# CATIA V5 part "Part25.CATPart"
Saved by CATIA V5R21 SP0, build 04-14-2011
Part number: Part25
Bounding box of the stored display mesh (mm): x 142.392 to 457.392, y 96.884 to 436.884, z 0 to 4
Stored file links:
  C:\Users\Administrator\Desktop\arm\Arm_Detailed_Design_Assembly_Manu\CAD\Part25.CATPart
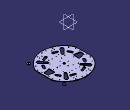
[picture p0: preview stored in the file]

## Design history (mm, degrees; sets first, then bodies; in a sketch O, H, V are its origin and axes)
Body1 (main body)
  Sketch1 on xy-plane, origin (0, 0, 0), H (1, 0, 0), V (0, 1, 0)
    circle A1 centre (152.3916, 324.3842) radius 2.5
    circle A2 centre (152.3916, 209.3842) radius 2.5
    circle A3 centre (242.3916, 414.3842) radius 2.5
    circle A4 centre (357.3916, 414.3842) radius 2.5
    circle A5 centre (447.3916, 324.3842) radius 2.5
    circle A6 centre (447.3916, 209.3842) radius 2.5
    circle A7 centre (242.3916, 119.3842) radius 2.5
    circle A8 centre (357.3916, 119.3842) radius 2.5
    arc A9 centre (299.8916, 266.8842) radius 170 from (144.0583, 198.9432) to (455.7249, 198.9432) ccw
    arc A10 centre (299.8916, 266.8842) radius 170 from (455.7249, 334.8251) to (144.0583, 334.8251) ccw
    arc A11 centre (162.3916, 206.9363) radius 20 from (142.3916, 206.9363) to (144.0583, 198.9432) ccw
    circle A12 centre (241.3916, 319.7117) radius 2
    circle A13 centre (241.3916, 399.7117) radius 2
    circle A14 centre (172.1096, 359.7117) radius 2
    circle A15 centre (358.3916, 319.7117) radius 2
    circle A16 centre (358.3916, 399.7117) radius 2
    circle A17 centre (427.6736, 359.7117) radius 2
    circle A18 centre (241.3916, 214.0566) radius 2
    circle A19 centre (241.3916, 134.0566) radius 2
    circle A20 centre (172.1096, 174.0566) radius 2
    circle A21 centre (358.3916, 214.0566) radius 2
    circle A22 centre (358.3916, 134.0566) radius 2
    circle A23 centre (427.6736, 174.0566) radius 2
    circle A24 centre (284.3916, 344.1678) radius 1.5
    circle A25 centre (315.3916, 344.1678) radius 1.5
    circle A26 centre (284.3916, 189.6006) radius 1.5
    circle A27 centre (315.3916, 189.6006) radius 1.5
    circle A28 centre (284.3916, 424.1678) radius 1.5
    circle A29 centre (315.3916, 424.1678) radius 1.5
    circle A30 centre (284.3916, 109.6006) radius 1.5
    circle A31 centre (315.3916, 109.6006) radius 1.5
    circle A32 centre (261.856, 348.4519) radius 1.5
    circle A33 centre (216.8916, 258.9342) radius 1.5
    circle A34 centre (337.9273, 348.4519) radius 1.5
    circle A35 centre (381.8916, 266.8842) radius 1.5
    circle A36 centre (261.856, 185.3165) radius 1.5
    circle A37 centre (337.9273, 185.3165) radius 1.5
    circle A38 centre (154.8916, 294.1984) radius 1.5
    circle A39 centre (154.8916, 239.57) radius 1.5
    circle A40 centre (262.3916, 401.7684) radius 1.5
    circle A41 centre (337.3916, 401.7684) radius 1.5
    circle A42 centre (262.3916, 132) radius 1.5
    circle A43 centre (337.3916, 132) radius 1.5
    circle A44 centre (268.0718, 266.8842) radius 2
    circle A45 centre (299.8916, 235.0644) radius 2
    circle A46 centre (299.8916, 298.704) radius 2
    circle A47 centre (331.7114, 266.8842) radius 2
    circle A48 centre (299.8916, 266.8842) radius 8
    circle A49 centre (444.8916, 294.1984) radius 1.5
    circle A50 centre (444.8916, 239.57) radius 1.5
    line L1 (142.3916, 326.8321) -> (142.3916, 206.9363)
    arc A51 centre (162.3916, 326.8321) radius 20 from (144.0583, 334.8251) to (142.3916, 326.8321) ccw
    arc A52 centre (437.3916, 206.9363) radius 20 from (455.7249, 198.9432) to (457.3916, 206.9363) ccw
    line L2 (457.3916, 326.8321) -> (457.3916, 206.9363)
    arc A53 centre (437.3916, 326.8321) radius 20 from (457.3916, 326.8321) to (455.7249, 334.8251) ccw
    line L3 (160.911, 251.0803) -> (200.911, 243.0803)
    arc A54 centre (201.8916, 247.9832) radius 5 from (200.911, 243.0803) to (206.8916, 247.9832) ccw
    line L4 (206.8916, 247.9832) -> (206.8916, 285.7852)
    arc A55 centre (201.8916, 285.7852) radius 5 from (206.8916, 285.7852) to (200.911, 290.6881) ccw
    line L5 (200.911, 290.6881) -> (160.911, 282.6881)
    arc A56 centre (161.8916, 277.7852) radius 5 from (160.911, 282.6881) to (156.8916, 277.7852) ccw
    line L6 (156.8916, 277.7852) -> (156.8916, 255.9832)
    arc A57 centre (161.8916, 255.9832) radius 5 from (156.8916, 255.9832) to (160.911, 251.0803) ccw
    line L7 (438.8722, 251.0803) -> (398.8722, 243.0803)
    arc A58 centre (397.8916, 247.9832) radius 5 from (392.8916, 247.9832) to (398.8722, 243.0803) ccw
    line L8 (392.8916, 247.9832) -> (392.8916, 285.7852)
    arc A59 centre (397.8916, 285.7852) radius 5 from (398.8722, 290.6881) to (392.8916, 285.7852) ccw
    line L9 (398.8722, 290.6881) -> (438.8722, 282.6881)
    arc A60 centre (437.8916, 277.7852) radius 5 from (442.8916, 277.7852) to (438.8722, 282.6881) ccw
    line L10 (442.8916, 277.7852) -> (442.8916, 255.9832)
    arc A61 centre (437.8916, 255.9832) radius 5 from (438.8722, 251.0803) to (442.8916, 255.9832) ccw
    line L11 (236.5736, 330.8185) -> (199.6905, 367.7016)
    line L12 (247.9237, 340.3423) -> (218.0056, 383.0698)
    arc A62 centre (240.3953, 337.7891) radius 7.9495 from (236.5736, 330.8185) to (247.9237, 340.3423) ccw
    arc A63 centre (208.1757, 376.1869) radius 12 from (218.0056, 383.0698) to (199.6905, 367.7016) ccw
    line L13 (363.2096, 330.8185) -> (400.0928, 367.7016)
    line L14 (351.8595, 340.3423) -> (381.7777, 383.0698)
    arc A64 centre (359.3879, 337.7891) radius 7.9495 from (351.8595, 340.3423) to (363.2096, 330.8185) ccw
    arc A65 centre (391.6075, 376.1869) radius 12 from (400.0928, 367.7016) to (381.7777, 383.0698) ccw
    line L15 (236.5736, 202.9499) -> (199.6905, 166.0668)
    line L16 (247.9237, 193.426) -> (218.0056, 150.6986)
    arc A66 centre (240.3953, 195.9793) radius 7.9495 from (247.9237, 193.426) to (236.5736, 202.9499) ccw
    arc A67 centre (208.1757, 157.5815) radius 12 from (199.6905, 166.0668) to (218.0056, 150.6986) ccw
    line L17 (363.2096, 202.9499) -> (400.0928, 166.0668)
    line L18 (351.8595, 193.426) -> (381.7777, 150.6986)
    arc A68 centre (359.3879, 195.9793) radius 7.9495 from (363.2096, 202.9499) to (351.8595, 193.426) ccw
    arc A69 centre (391.6075, 157.5815) radius 12 from (381.7777, 150.6986) to (400.0928, 166.0668) ccw
    arc A70 centre (299.8916, 266.8842) radius 125 from (196.6789, 337.3976) to (184.8285, 315.7256) ccw
    arc A71 centre (299.8916, 266.8842) radius 110 from (209.0645, 328.936) to (198.6361, 309.8646) ccw
    arc A72 centre (202.8717, 333.1668) radius 7.5 from (209.0645, 328.936) to (196.6789, 337.3976) ccw
    arc A73 centre (191.7323, 312.7951) radius 7.5 from (184.8285, 315.7256) to (198.6361, 309.8646) ccw
    arc A74 centre (299.8916, 266.8842) radius 125 from (184.8285, 218.0428) to (196.6789, 196.3708) ccw
    arc A75 centre (299.8916, 266.8842) radius 125 from (244.4288, 154.8624) to (270.3723, 145.4197) ccw
    arc A76 centre (299.8916, 266.8842) radius 110 from (251.0844, 168.305) to (273.9147, 159.9955) ccw
    arc A77 centre (299.8916, 266.8842) radius 110 from (198.6361, 223.9038) to (209.0645, 204.8324) ccw
    arc A78 centre (272.1435, 152.7076) radius 7.5 from (270.3723, 145.4197) to (273.9147, 159.9955) ccw
    arc A79 centre (247.7566, 161.5837) radius 7.5 from (251.0844, 168.305) to (244.4288, 154.8624) ccw
    arc A80 centre (202.8717, 200.6016) radius 7.5 from (196.6789, 196.3708) to (209.0645, 204.8324) ccw
    arc A81 centre (191.7323, 220.9733) radius 7.5 from (198.6361, 223.9038) to (184.8285, 218.0428) ccw
    arc A82 centre (299.8916, 266.8842) radius 125 from (414.9547, 315.7256) to (403.1043, 337.3976) ccw
    arc A83 centre (299.8916, 266.8842) radius 110 from (401.1471, 309.8646) to (390.7188, 328.936) ccw
    arc A84 centre (396.9115, 333.1668) radius 7.5 from (403.1043, 337.3976) to (390.7188, 328.936) ccw
    arc A85 centre (408.0509, 312.7951) radius 7.5 from (401.1471, 309.8646) to (414.9547, 315.7256) ccw
    arc A86 centre (299.8916, 266.8842) radius 125 from (403.1043, 196.3708) to (414.9547, 218.0428) ccw
    arc A87 centre (299.8916, 266.8842) radius 110 from (390.7188, 204.8324) to (401.1471, 223.9038) ccw
    arc A88 centre (396.9115, 200.6016) radius 7.5 from (390.7188, 204.8324) to (403.1043, 196.3708) ccw
    arc A89 centre (408.0509, 220.9733) radius 7.5 from (414.9547, 218.0428) to (401.1471, 223.9038) ccw
    arc A90 centre (299.8916, 266.8842) radius 125 from (329.4109, 145.4197) to (355.3544, 154.8624) ccw
    arc A91 centre (299.8916, 266.8842) radius 110 from (325.8686, 159.9955) to (348.6988, 168.305) ccw
    arc A92 centre (327.6397, 152.7076) radius 7.5 from (325.8686, 159.9955) to (329.4109, 145.4197) ccw
    arc A93 centre (352.0266, 161.5837) radius 7.5 from (355.3544, 154.8624) to (348.6988, 168.305) ccw
    arc A94 centre (299.8916, 266.8842) radius 125 from (270.3723, 388.3486) to (244.4288, 378.906) ccw
    arc A95 centre (299.8916, 266.8842) radius 110 from (273.9147, 373.7729) to (251.0844, 365.4634) ccw
    arc A96 centre (272.1435, 381.0608) radius 7.5 from (273.9147, 373.7729) to (270.3723, 388.3486) ccw
    arc A97 centre (247.7566, 372.1847) radius 7.5 from (244.4288, 378.906) to (251.0844, 365.4634) ccw
    arc A98 centre (299.8916, 266.8842) radius 125 from (355.3544, 378.906) to (329.4109, 388.3486) ccw
    arc A99 centre (299.8916, 266.8842) radius 110 from (348.6988, 365.4634) to (325.8686, 373.7729) ccw
    arc A100 centre (327.6397, 381.0608) radius 7.5 from (329.4109, 388.3486) to (325.8686, 373.7729) ccw
    arc A101 centre (352.0266, 372.1847) radius 7.5 from (348.6988, 365.4634) to (355.3544, 378.906) ccw
    point P1 (144.0583, 198.9432)
    point P2 (455.7249, 198.9432)
    point P3 (455.7249, 334.8251)
    point P4 (144.0583, 334.8251)
    point P5 (142.3916, 206.9363)
    point P6 (144.0583, 198.9432)
    point P7 (142.3916, 326.8321)
    point P8 (142.3916, 206.9363)
    point P9 (144.0583, 334.8251)
    point P10 (142.3916, 326.8321)
    point P11 (455.7249, 198.9432)
    point P12 (457.3916, 206.9363)
    point P13 (457.3916, 326.8321)
    point P14 (457.3916, 206.9363)
    point P15 (457.3916, 326.8321)
    point P16 (455.7249, 334.8251)
    point P17 (160.911, 251.0803)
    point P18 (200.911, 243.0803)
    point P19 (200.911, 243.0803)
    point P20 (206.8916, 247.9832)
    point P21 (206.8916, 247.9832)
    point P22 (206.8916, 285.7852)
    point P23 (206.8916, 285.7852)
    point P24 (200.911, 290.6881)
    point P25 (200.911, 290.6881)
    point P26 (160.911, 282.6881)
    point P27 (160.911, 282.6881)
    point P28 (156.8916, 277.7852)
    point P29 (156.8916, 277.7852)
    point P30 (156.8916, 255.9832)
    point P31 (156.8916, 255.9832)
    point P32 (160.911, 251.0803)
    point P33 (438.8722, 251.0803)
    point P34 (398.8722, 243.0803)
    point P35 (392.8916, 247.9832)
    point P36 (398.8722, 243.0803)
    point P37 (392.8916, 247.9832)
    point P38 (392.8916, 285.7852)
    point P39 (398.8722, 290.6881)
    point P40 (392.8916, 285.7852)
    point P41 (398.8722, 290.6881)
    point P42 (438.8722, 282.6881)
    point P43 (442.8916, 277.7852)
    point P44 (438.8722, 282.6881)
    point P45 (442.8916, 277.7852)
    point P46 (442.8916, 255.9832)
    point P47 (438.8722, 251.0803)
    point P48 (442.8916, 255.9832)
    point P49 (236.5736, 330.8185)
    point P50 (199.6905, 367.7016)
    point P51 (247.9237, 340.3423)
    point P52 (218.0056, 383.0698)
    point P53 (236.5736, 330.8185)
    point P54 (247.9237, 340.3423)
    point P55 (218.0056, 383.0698)
    point P56 (199.6905, 367.7016)
    point P57 (363.2096, 330.8185)
    point P58 (400.0928, 367.7016)
    point P59 (351.8595, 340.3423)
    point P60 (381.7777, 383.0698)
    point P61 (351.8595, 340.3423)
    point P62 (363.2096, 330.8185)
    point P63 (400.0928, 367.7016)
    point P64 (381.7777, 383.0698)
    point P65 (236.5736, 202.9499)
    point P66 (199.6905, 166.0668)
    point P67 (247.9237, 193.426)
    point P68 (218.0056, 150.6986)
    point P69 (247.9237, 193.426)
    point P70 (236.5736, 202.9499)
    point P71 (199.6905, 166.0668)
    point P72 (218.0056, 150.6986)
    point P73 (363.2096, 202.9499)
    point P74 (400.0928, 166.0668)
    point P75 (351.8595, 193.426)
    point P76 (381.7777, 150.6986)
    point P77 (363.2096, 202.9499)
    point P78 (351.8595, 193.426)
    point P79 (381.7777, 150.6986)
    point P80 (400.0928, 166.0668)
    point P81 (196.6789, 337.3976)
    point P82 (184.8285, 315.7256)
    point P83 (209.0645, 328.936)
    point P84 (198.6361, 309.8646)
    point P85 (209.0645, 328.936)
    point P86 (196.6789, 337.3976)
    point P87 (184.8285, 315.7256)
    point P88 (198.6361, 309.8646)
    point P89 (184.8285, 218.0428)
    point P90 (196.6789, 196.3708)
    point P91 (244.4288, 154.8624)
    point P92 (270.3723, 145.4197)
    point P93 (251.0844, 168.305)
    point P94 (273.9147, 159.9955)
    point P95 (198.6361, 223.9038)
    point P96 (209.0645, 204.8324)
    point P97 (270.3723, 145.4197)
    point P98 (273.9147, 159.9955)
    point P99 (251.0844, 168.305)
    point P100 (244.4288, 154.8624)
    point P101 (196.6789, 196.3708)
    point P102 (209.0645, 204.8324)
    point P103 (198.6361, 223.9038)
    point P104 (184.8285, 218.0428)
    point P105 (414.9547, 315.7256)
    point P106 (403.1043, 337.3976)
    point P107 (401.1471, 309.8646)
    point P108 (390.7188, 328.936)
    point P109 (403.1043, 337.3976)
    point P110 (390.7188, 328.936)
    point P111 (401.1471, 309.8646)
    point P112 (414.9547, 315.7256)
    point P113 (403.1043, 196.3708)
    point P114 (414.9547, 218.0428)
    point P115 (390.7188, 204.8324)
    point P116 (401.1471, 223.9038)
    point P117 (390.7188, 204.8324)
    point P118 (403.1043, 196.3708)
    point P119 (414.9547, 218.0428)
    point P120 (401.1471, 223.9038)
    point P121 (329.4109, 145.4197)
    point P122 (355.3544, 154.8624)
    point P123 (325.8686, 159.9955)
    point P124 (348.6988, 168.305)
    point P125 (325.8686, 159.9955)
    point P126 (329.4109, 145.4197)
    point P127 (355.3544, 154.8624)
    point P128 (348.6988, 168.305)
    point P129 (270.3723, 388.3486)
    point P130 (244.4288, 378.906)
    point P131 (273.9147, 373.7729)
    point P132 (251.0844, 365.4634)
    point P133 (273.9147, 373.7729)
    point P134 (270.3723, 388.3486)
    point P135 (244.4288, 378.906)
    point P136 (251.0844, 365.4634)
    point P137 (355.3544, 378.906)
    point P138 (329.4109, 388.3486)
    point P139 (348.6988, 365.4634)
    point P140 (325.8686, 373.7729)
    point P141 (329.4109, 388.3486)
    point P142 (325.8686, 373.7729)
    point P143 (348.6988, 365.4634)
    point P144 (355.3544, 378.906)
    axis line L19 (299.8916, 266.8842) -> (478.6353, 266.8842)
    point P145 (299.8916, 266.8842)
    circle A102 centre (437.2505, 405.4668) radius 9.75
    circle A103 centre (437.2505, 405.4668) radius 1.5
    circle A104 centre (437.2505, 128.3016) radius 9.75
    circle A105 centre (437.2505, 128.3016) radius 1.5
    circle A106 centre (352.3916, 266.8842) radius 2.5
    point P149 (352.3916, 266.8842)
    circle A107 centre (273.6416, 312.3505) radius 2.5
    circle A108 centre (273.6416, 221.4179) radius 2.5
    radius A102 = 9.75
    radius A103 = 1.5
    radius A106 = 2.5
    distance P145 P149 = 52.5
    fix: P1, P2, P3, P4, P5, P6, P7, P8, P9, P10, P11, P12, P13, P14, P15, P16, P17, P18, P19, P20, P21, P22, P23, P24, P25, P26, P27, P28, P29, P30, P31, P32, P33, P34, P35, P36, P37, P38, P39, P40, P41, P42, P43, P44, P45, P46, P47, P48, P49, P50, P51, P52, P53, P54, P55, P56, P57, P58, P59, P60, P61, P62, P63, P64, P65, P66, P67, P68, P69, P70, P71, P72, P73, P74, P75, P76, P77, P78, P79, P80, P81, P82, P83, P84, P85, P86, P87, P88, P89, P90, P91, P92, P93, P94, P95, P96, P97, P98, P99, P100, P101, P102, P103, P104, P105, P106, P107, P108, P109, P110, P111, P112, P113, P114, P115, P116, P117, P118, P119, P120, P121, P122, P123, P124, P125, P126, P127, P128, P129, P130, P131, P132, P133, P134, P135, P136, P137, P138, P139, P140, P141, P142, P143, P144, A1, A2, A3, A4, A5, A6, A7, A8, A9, A10, A11, A12, A13, A14, A15, A16, A17, A18, A19, A20, A21, A22, A23, A24, A25, A26, A27, A28, A29, A30, A31, A32, A33, A34, A35, A36, A37, A38, A39, A40, A41, A42, A43, A44, A45, A46, A47, A48, A49, A50, L1, A51, A52, L2, A53, L3, A54, L4, A55, L5, A56, L6, A57, L7, A58, L8, A59, L9, A60, L10, A61, L11, L12, A62, A63, L13, L14, A64, A65, L15, L16, A66, A67, L17, L18, A68, A69, A70, A71, A72, A73, A74, A75, A76, A77, A78, A79, A80, A81, A82, A83, A84, A85, A86, A87, A88, A89, A90, A91, A92, A93, A94, A95, A96, A97, A98, A99, A100, A101
    concentricity: P145 A48
    horizontal: L19 H
    symmetry: A102 A104 L19, A103 A105 L19
    coincidence: P149 L19
  Pad1: profile Sketch1, direction (0, 0, 1), length 4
